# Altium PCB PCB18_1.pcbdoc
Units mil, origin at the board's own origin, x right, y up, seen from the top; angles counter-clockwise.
Board outline 2300 x 1655 mil, 2 copper layers (Top Layer, Bottom Layer); 38 components, 30 nets, 133 pads, 17 vias.
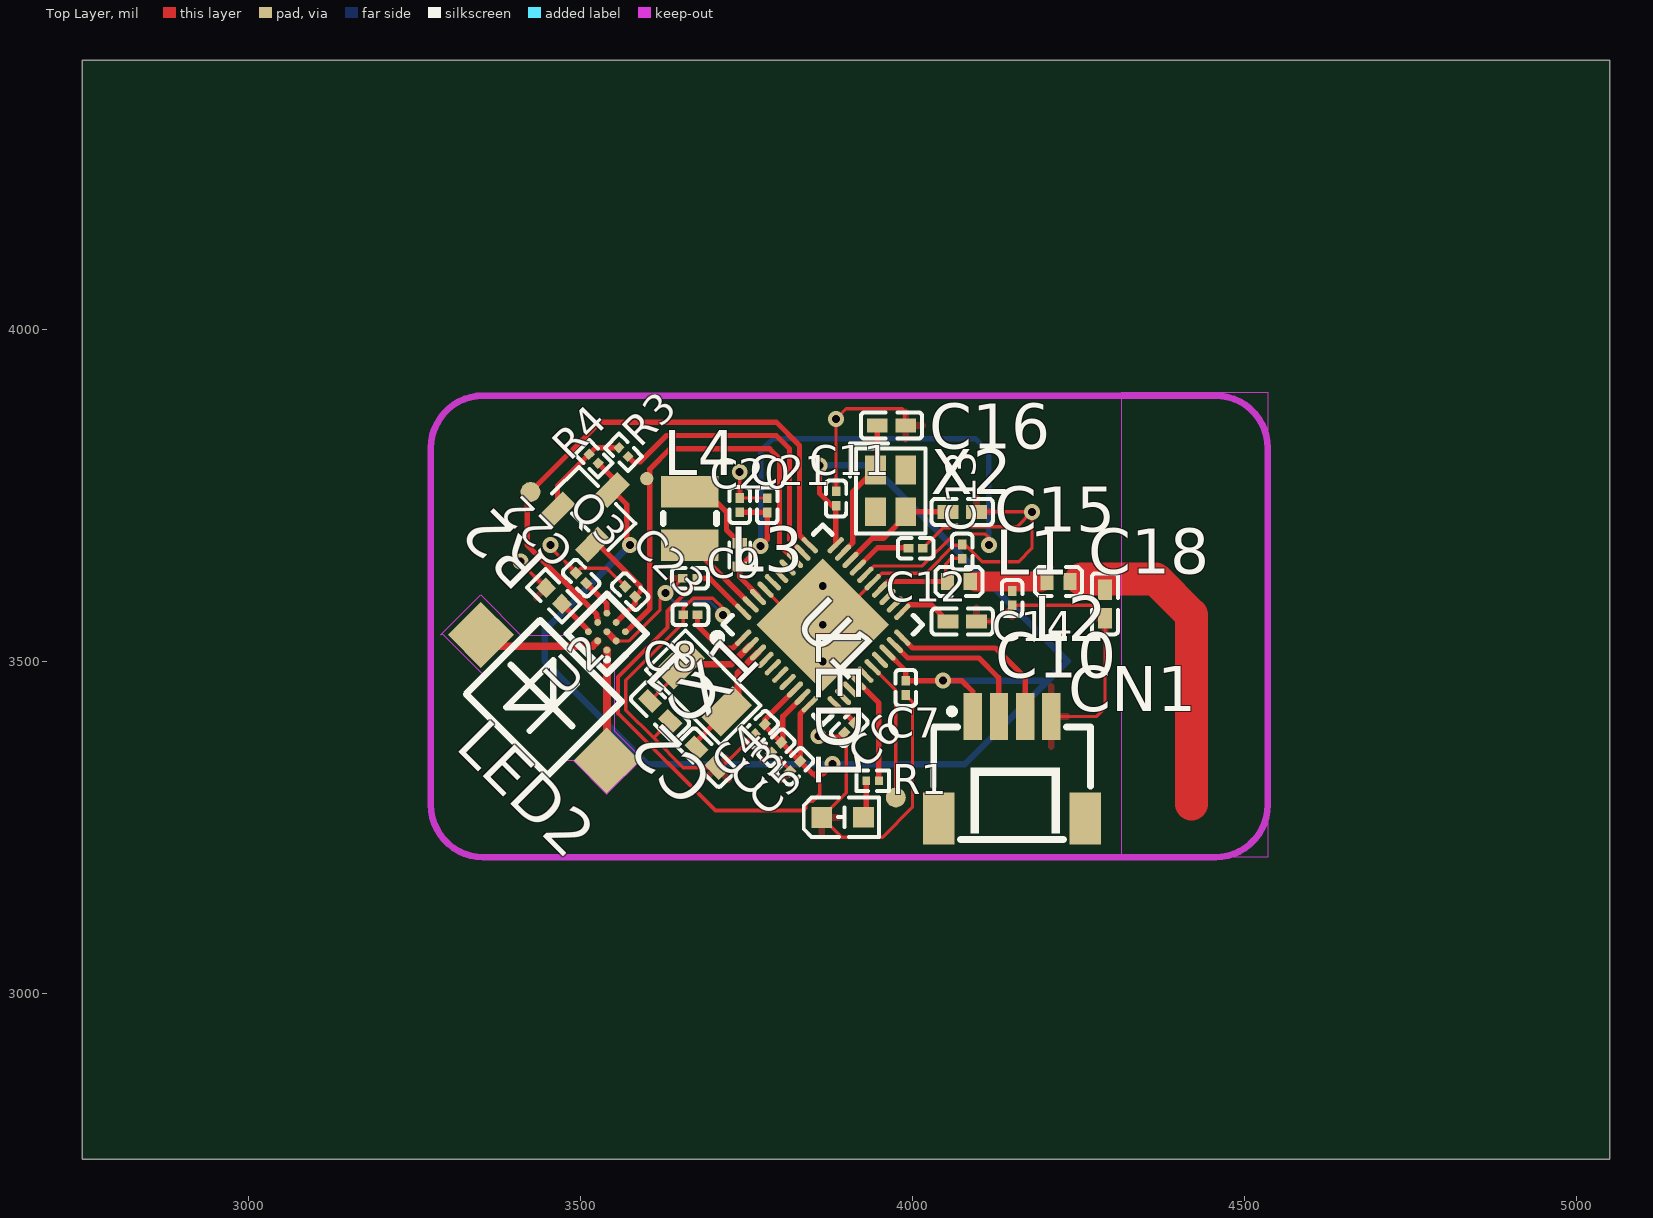
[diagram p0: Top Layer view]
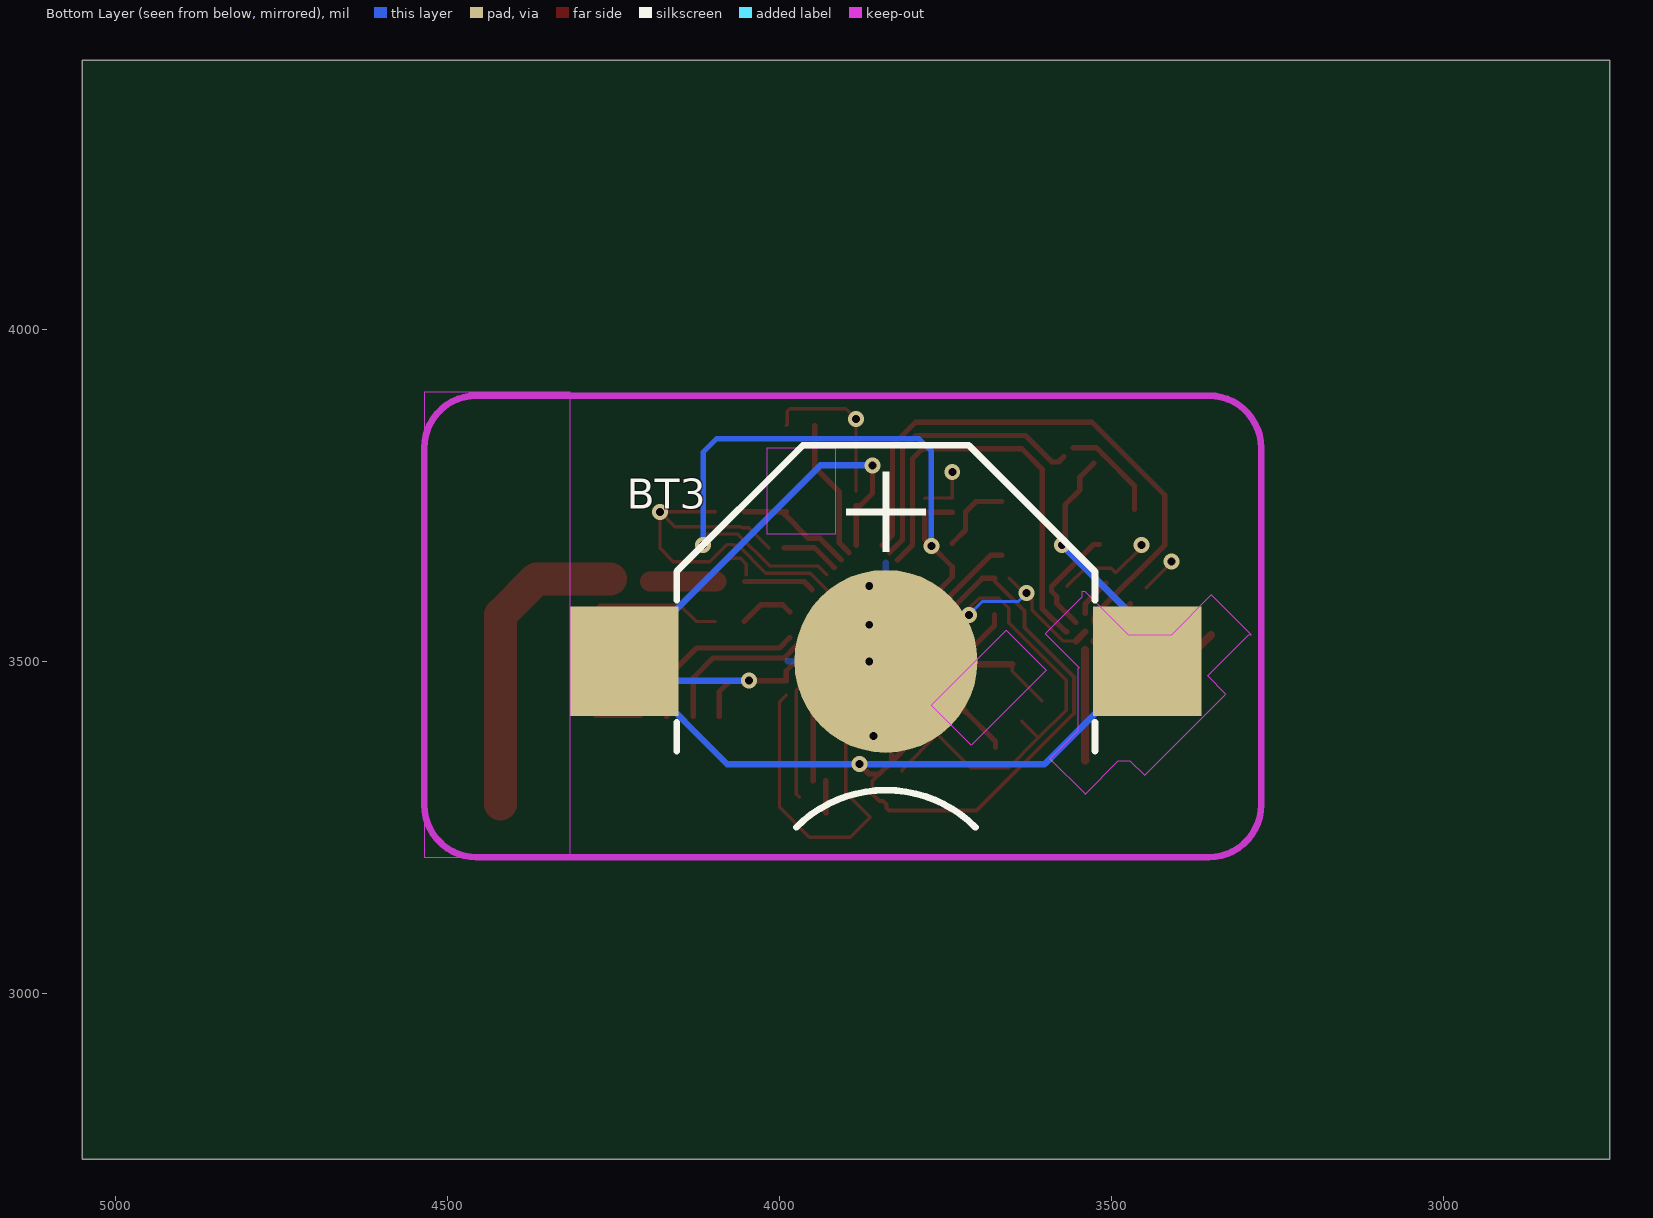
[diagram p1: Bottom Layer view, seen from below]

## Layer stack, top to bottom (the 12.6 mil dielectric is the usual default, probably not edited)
Top Layer: signal copper (thickness not stored)
Dielectric: dielectric 12.6, FR-4, Dk 4.8
Bottom Layer: signal copper (thickness not stored)

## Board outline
5050,2750 2750,2750 2750,4405 5050,4405

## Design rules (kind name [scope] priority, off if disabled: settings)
BoardOutlineClearance safeClearance [All] p0: genericclearance=10 ignorepadtopadclearanceinfootprint=FALSE except(0: Arc-SplitContinuation Track-SplitContinuation SMDPad-SplitContinuation THPad-SplitContinuation Via-SplitContinuation Fill-SplitContinuation Poly-SplitContinuation Region-SplitContinuation Text-SplitContinuation; 6: Track-CutoutEdge SMDPad-CutoutEdge THPad-CutoutEdge Via-CutoutEdge Fill-CutoutEdge Region-CutoutEdge; 11.8: Track-OutlineEdge SMDPad-OutlineEdge THPad-OutlineEdge Via-OutlineEdge Fill-OutlineEdge Region-OutlineEdge Poly-OutlineEdge Text-OutlineEdge)
Clearance safeClearance [(InNet('XL1') OR InNet('XL2') OR InNet('$1N2289') OR InNet('$1N2530') OR InNet('GND') OR InNet('$1N3495') OR InNet('SWDCLK') OR InNet('SWDIO') OR InNet('RESET') OR InNet('VDD_NRF') OR InNet('$1N2985') OR InNet('$1N3242') OR InNet('DEC4') OR InNet('XC1') OR InNet('XC2') OR InNet('DCC') OR InNet('$1N6091') OR InNet('E/CFGCLK') OR InNet('D/CFGDATA') OR InNet('$1N11204') OR InNet('$1N11226') OR InNet('$1N11357') OR InNet('$1N9430') OR InNet('$1N23087') OR InNet('$1N22902') OR InNet('LED') OR InNet('$1N29852') OR InNet('$1N28962') OR InNet('POWER_TS4231') OR InNet('$1N31595'))] p1: gap=7 ignorepadtopadclearanceinfootprint=FALSE except(6: Track-Track Track-SMDPad SMDPad-SMDPad Track-THPad SMDPad-THPad THPad-THPad Track-Via SMDPad-Via THPad-Via Via-Via Track-Fill SMDPad-Fill THPad-Fill Via-Fill Fill-Fill Track-Region SMDPad-Region THPad-Region Via-Region Fill-Region Region-Region Track-Poly SMDPad-Poly THPad-Poly Via-Poly Fill-Poly Region-Poly Poly-Poly Track-Text SMDPad-Text THPad-Text Via-Text Fill-Text Region-Text Poly-Text Text-Text Track-Hole SMDPad-Hole THPad-Hole Via-Hole Fill-Hole Region-Hole Poly-Hole Text-Hole; 11.8: Track-Sheet SMDPad-Sheet THPad-Sheet Via-Sheet Fill-Sheet Region-Sheet Poly-Sheet Text-Sheet Sheet-Hole)
DiffPairsRouting differentialPair [All] p1: maxuncoupledlength=10 minlimit=6 maxlimit=6 mostfreqgap=6 toplayer_minwidth=5 toplayer_prefwidth=10 toplayer_maxwidth=100 bottomlayer_minwidth=5 bottomlayer_prefwidth=10 bottomlayer_maxwidth=100
PasteMaskExpansion pasteMaskExpansion [All] p1: expansion=0
PlaneConnect innerPlane [All] p1: planeconnectstyle=Relief reliefexpansion=20 reliefentries=4 reliefconductorwidth=10 reliefairgap=10
PolygonConnect copperRegion [All] p1: connectstyle=Relief reliefentries=4 reliefconductorwidth=10 polygonreliefangle="90 Angle" airgapwidth=10
RoutingVias viaSize [All] p1: viastyle="Through Hole" holewidth=12 minholewidth=11.8 maxholewidth=236.2 width=24 minwidth=19.7 maxwidth=393.7
SolderMaskExpansion solderMaskExpansion [All] p1: useseparateexpansions=TRUE expansion=4 expansionbottom=4
Width trackWidth [All] p1: maxlimit=50 minlimit=5 preferedwidth=8

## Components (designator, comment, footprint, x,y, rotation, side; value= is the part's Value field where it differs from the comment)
BT3 "MY-1632-03" BAT-SMD_MY-1632-03 3840,3500 r180 bottom
C1 "GRM1555C1H120JA01D" C0402 3620,3425 r135 top
C2 "GRM1555C1H120JA01D" C0402 3690,3355 r135 top
C3 "GRM035R60J475ME15D" C0201 3795,3370 r225 top
C4 "GRM035R60J475ME15D" C0201 3770.13,3397.46 r225 top
C5 "GRM035R60J475ME15D" C0201 3823.28,3341.72 r225 top
C6 "GRM035R60J475ME15D" C0201 3905,3400 r225 top
C7 "GRM033R61E104KE14D" C0201 3990,3460 r90 top
C8 "GRM033R61E104KE14D" C0201 3665.6,3570 r180 top
C9 "GRM033R61A105ME44D" C0201 3665,3625 r180 top
C10 "CC0402KRX7R9BB821" C0402 4075,3560 r0 top
C11 "GRM033R61E104KE14D" C0201 3885,3745 r90 top
C12 "GRM033R61E104KE14D" C0201 4005,3670 r0 top
C13 "GRM0335C1H1R0BA01D" C0201 4075,3665 r90 top
C14 "GRM0335C1H1R2BA01D" C0201 4150,3595 r90 top
C15 "GRM1555C1H120JA01D" C0402 4075,3725 r0 top
C16 "GRM1555C1H120JA01D" C0402 3968.54,3855 r0 top
C18 "GRM1555C1H120JA01D" C0402 4290,3586.46 r90 top
C20 "CGA0201X5R473K160ET" C0201 3740,3735 r270 top
C21 "GRM033R61A105ME44D" C0201 3781.37,3734.88 r270 top
C22 "GRM033R61A105ME44D" C0201 3501.16,3625.33 r135 top
C23 "GRM033R61E104KE14D" C0201 3575,3605 r135 top
CN1 "1.0-4PWB" CONN-SMD_4P-P1.00_DEALON_1.0-4PWB 4150,3340 r0 top
L1 "LQW15AN4N7B00D" IND-SMD_L1.0-W0.6 4070,3620 r0 top
L2 "LQW15AN2N2B80D" IND-SMD_L1.0-W0.6 4220,3620 r0 top
L3 "LQW15AN15NG00D" IND-SMD_L1.0-W0.5-2 3740,3660 r270 top
L4 "FTC252012S100MBCA" IND-SMD_L2.5-W2.0 3665,3715 r90 top
LED1 "NCD0603G1" LED0603-RD_1 3895,3265 r0 top
LED2 "VBPW34S" SENSOR-SMD_L4.4-W3.9 3445,3445 r315 top
Q3 "HL3407A" SOT-23-3_L2.9-W1.3-P1.90-LS2.4-BL-1 3520,3730 r315 top
R1 "0201WMF1002TEE" R0201 3940,3320 r180 top
R2 "0402WGF1502TCE" R0402 3460.2,3598.51 r315 top
R3 "0201WMF1001TEE" R0201 3565,3815 r135 top
R4 "0201WMF1001TEE" R0201 3520,3805 r315 top
U1 "nRF52833-QDAA-R" QFN-40_L5.0-W5.0-P0.40-TL-EP3.6 3865,3555 r45 top
U2 "TS4231" TS4231 3540,3545 r135 top
X1 "X321532768KGD2SI" OSC-SMD_L3.2-W1.5 3685,3460.2 r135 top
X2 "X201632MOB4SI" CRYSTAL-SMD_4P-L2.0-W1.6-BL-2 3967.36,3756.49 r270 top

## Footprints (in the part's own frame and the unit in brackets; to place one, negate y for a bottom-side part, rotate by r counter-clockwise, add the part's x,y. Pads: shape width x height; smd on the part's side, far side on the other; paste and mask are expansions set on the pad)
BAT-SMD_MY-1632-03 [mm]
  rect 4.15x4.2 smd: 1(-10,0) 1(10,0)
  round 7 smd: 2(0,0)
  silkscreen extent -8,-6.35 8,8.25
C0201 [mil]
  rect 14.51x12.76 smd: 1(-10.8,0) 2(10.8,0)
  silkscreen extent -27,-15 27,15
C0402 [mm]
  rect 0.79x0.54 smd: 1(-0.545,0) 2(0.545,0)
  silkscreen extent -1.17,-0.5 1.17,0.5
CONN-SMD_4P-P1.00_DEALON_1.0-4PWB [mm]
  rect 0.7x1.8 smd: 1(-1.5,1.95) 2(-0.5,1.95) 3(0.5,1.95) 4(1.5,1.95)
  rect 1.2x2 smd: 5(2.8,-1.95) 6(-2.8,-1.95)
  silkscreen extent -3,-2.75 3,2.25
CRYSTAL-SMD_4P-L2.0-W1.6-BL-2 [mm]
  rect 1.1x0.8 smd: 1(-0.8,-0.575) 2(0.8,-0.575) 3(0.8,0.575) 4(-0.8,0.575)
  silkscreen extent -1.82,-1.56 1.64,1.33
IND-SMD_L1.0-W0.5-2 [mm]
  rect 0.4x0.55 smd: 1(-0.45,0) 2(0.45,0)
  silkscreen extent -0.5,-0.41 0.5,0.41
IND-SMD_L1.0-W0.6 [mm]
  rect 0.5x0.648 smd: 1(-0.434,0) 2(0.434,0)
  silkscreen extent -0.9,-0.55 0.9,0.55
IND-SMD_L2.5-W2.0 [mm]
  rect 1.2x2.2 smd: 1(1.028,0) 2(-1.028,0)
  silkscreen extent -0.2,-1.02 0.2,1.02
LED0603-RD_1 [mm]
  rect 0.8x0.8 smd: 1(-0.799,-0.004) 2(0.799,0.004)
  silkscreen extent -1.49,-0.75 1.39,0.76
OSC-SMD_L3.2-W1.5 [mm]
  rect 1.05x1.7 smd: 1(-1.275,0) 2(1.275,0)
  silkscreen extent -2.03,-1.08 2.03,1.08
QFN-40_L5.0-W5.0-P0.40-TL-EP3.6 [mm]
  oval 0.8x0.2 smd: 1(-2.499,1.8) 2(-2.499,1.4) 3(-2.499,1) 4(-2.499,0.6) 5(-2.499,0.2) 6(-2.499,-0.2) 7(-2.499,-0.6) 8(-2.499,-1) 9(-2.499,-1.4) 10(-2.499,-1.8) 21(2.499,-1.8) 22(2.499,-1.4) 23(2.499,-1) 24(2.499,-0.6) 25(2.499,-0.2) 26(2.499,0.2) 27(2.499,0.6) 28(2.499,1) 29(2.499,1.4) 30(2.499,1.8)
  oval 0.2x0.8 smd: 11(-1.8,-2.499) 12(-1.4,-2.499) 13(-1,-2.499) 14(-0.6,-2.499) 15(-0.2,-2.499) 16(0.2,-2.499) 17(0.6,-2.499) 18(1,-2.499) 19(1.4,-2.499) 20(1.8,-2.499) 31(1.8,2.499) 32(1.4,2.499) 33(1,2.499) 34(0.6,2.499) 35(0.2,2.499) 36(-0.2,2.499) 37(-0.6,2.499) 38(-1,2.499) 39(-1.4,2.499) 40(-1.8,2.499)
  rect 3.6x3.6 smd: 41(0,0)
  silkscreen extent -3.35,-2.7 2.7,2.7
R0201 [mil]
  rect 11.93x12.76 smd: 1(-9.51,0) 2(9.51,0)
  silkscreen extent -24,-15 24,15
R0402 [mm]
  rect 0.566x0.54 smd: 1(-0.433,0) 2(0.433,0)
  silkscreen extent -0.94,-0.5 0.94,0.5
SENSOR-SMD_L4.4-W3.9 [mm]
  rect 1.8x1.8 smd: 1(-3.4,0) 2(3.4,0)
  silkscreen extent -2.2,-2 2.2,2
SOT-23-3_L2.9-W1.3-P1.90-LS2.4-BL-1 [mm]
  rect 0.7x1.25 smd: 1(-0.95,-1) 2(0.95,-1) 3(0,1)
  silkscreen extent -1.53,-0.73 1.53,0.73
TS4231 [mil]
  round 10.31 smd: 1(-20,20) 2(-0.32,20) 3(19.37,20) 4(-20,0.32) 5(-0.32,0.32) 6(19.37,0.32) 7(-20,-19.37) 8(-0.32,-19.37) 9(19.37,-19.37)
  silkscreen extent -45,-40 40,45

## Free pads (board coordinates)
  round 30 smd: 1(3425,3755) 1(3975,3295)
  round 20 smd: 1(3600,3775)

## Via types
v1: diameter 24.02, hole 12.01, Top Layer to Bottom Layer, 17 vias

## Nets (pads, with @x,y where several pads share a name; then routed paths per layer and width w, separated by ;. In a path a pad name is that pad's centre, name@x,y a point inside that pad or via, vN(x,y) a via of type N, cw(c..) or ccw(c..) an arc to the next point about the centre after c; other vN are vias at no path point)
$1N2289: C10.1 U1.21 | length 83.6
  Top Layer w8: U1.21 3995.22,3585 4028.54,3585 C10.1
$1N2530: C13.1 L1.1 U1.24 | length 152
  Top Layer w5: L1.1@4050,3630 4050,3646.42 4058.58,3655 4074.2,3655 C13.1
  Top Layer w8: U1.24 3963.4,3620 L1.1
$1N2985: C14.2 L1.2 L2.1 | length 100
  Top Layer w30: L1.2@4095,3620 L2.1@4195,3620
$1N3242: C18.2 L2.2 | length 472.4
  Top Layer w50: 4255,3624.06 4365.94,3624.06 4420,3570 4420,3285
$1N3495: C12.1 U1.27 | length 87.6
  Top Layer w8: U1.27 3918.22,3641.63 ccw(c3909.3,3652.42) 3919.2,3642.52 3947.68,3671 C12.1@3993.2,3671
$1N6091: L3.1 L4.1 | length 117
  Top Layer w8: L4.1@3665,3740.48 3704.52,3740.48 3720,3725 3720,3697.72 L3.1
$1N9430: C22.1 U2.9 | length 58.2
  Top Layer w8: C22.1 3540,3586.49 U2.9
$1N11204: LED2.2 U2.1 | length 166.5
  Top Layer w12: LED2.2 3540,3350.69 U2.1
$1N11226: LED2.1 U2.2 | length 186.1
  Top Layer w12: LED2.1 3367.36,3522.64 3518.08,3522.64 U2.2
$1N11357: R2.2 U2.3 | length 58.4
  Top Layer w8: R2.2 3512.16,3546.55 U2.3
$1N22902: LED1.2 R1.2 | length 48.8
  Top Layer w8: LED1.2@3929.86,3271.47 3930.49,3272.1 R1.2
$1N23087: C8.1 U1.1 | length 105.7
  Top Layer w8: C8.1 3676.4,3553.6 3710,3520 3729.77,3520 U1.1
$1N28962: C23.1 Q3.2 U2.8 | length 167.5
  Top Layer w8: Q3.2 3527.45,3675.72 3590.64,3612.53 3590.64,3605.36 C23.1 3582.64,3587.19 U2.8
$1N29852: C6.1 U1.11 | length 39.6
  Top Layer w8: U1.11 3884.97,3435.31 C6.1
$1N31595: Q3.1 R3.2 R4.1 | length 152
  Top Layer w8: Q3.1 3465.72,3764.17 R4.1 3523.28,3821.72 R3.2
D/CFGDATA: pad.1@3425,3755 U1.31 U2.6 | length 862.4
  Top Layer w8: U2.6 3526.08,3564.88 3524.84,3566.11 3524.84,3570.16 3420,3675 3420,3750 3530,3860 3795,3860 3830,3825 3830,3690 3845.31,3674.69 U1.31
DCC: L4.2 U1.39 | length 122.1
  Top Layer w8: L4.2@3665,3659.52 3682.53,3659.52 U1.39
DEC4: C20.2 C21.2 L3.2 U1.26 U1.38 | length 1064.6
  Top Layer w5: U1.26 3942.37,3643.5 4014.95,3643.5 4063,3691.55 4110,3691.55 4115,3686.55 v1(4115,3675)
  Top Layer w8: C20.2 C21.2@3781.25,3724.2 ; U1.38 3767.58,3599.3 3740,3626.88 L3.2 v1(3771.47,3673.75) 3781.25,3683.53 C21.2@3781.25,3724.2 ; C21.2 C21.2@3781.25,3724.2
  Bottom Layer w8: v1(3771.47,3673.75) 3771.47,3816.47 3790,3835 4095,3835 4115,3815 v1(4115,3675)
E/CFGCLK: pad.1@3600,3775 U1.33 U2.7 | length 638.1
  Top Layer w8: U2.7 3569.55,3544.55 3604.64,3579.64 3604.64,3789.64 3635,3820 3785,3820 3800,3805 3800,3675 3822.58,3652.42 U1.33
GND: BT3.2 C1.1 C2.1 C3.2 C4.2 C5.2 C6.2 C7.1 C8.2 C9.2 C10.2 C11.2 C12.2 C13.2 C14.1 C15.2 C16.2 C18.1 C20.1 C21.1 C22.2 C23.2 CN1.4 LED1.1 R2.1 U1.25 U1.37 U1.41 U2.4 U2.5 | length 3205.5
  Top Layer w5: v1(3410,3650) 3410,3648.71 R2.1 ; v1(3455,3675) 3455,3671.49 C22.2 3500.63,3640.07 3539.93,3640.07 C23.2 ; U2.4 3573.31,3530.64 3620,3577.32 3620,3594.15 v1(3628.43,3602.58) 3631.78,3602.58 C9.2 ; C1.1 3610.24,3384.89 3610.24,3384.76 ; v1(3715,3570) 3715,3579.73 3699.73,3595 3670,3595 3654.8,3579.8 C8.2 3654.8,3557.88 3568.5,3471.58 3568.5,3426.5 3610.24,3384.76 ; v1(3740,3785) C20.1 3781.25,3745.8 C21.1 ; U1.37 3831.59,3555 v1(3865,3555) 3876.13,3555 U1.25 3953.63,3632.5 4020.53,3632.5 4062.52,3674.5 4068.7,3674.5 4070,3675.8 C13.2 4079.2,3675.8 4105,3650 4160,3650 4180,3670 v1(4180,3725) ; C5.2 3815.65,3336.67 C4.2 3712.5,3339.83 C2.1 3655.17,3339.83 3610.24,3384.76 ; v1(3858.39,3387.24) 3892.24,3387.24 C6.2 3900.51,3389.22 3900.51,3301.84 LED1.1 3893.38,3235 3955,3235 4000,3280 4000,3439.2 C7.1 ; C11.2 v1(3885,3865) 3900,3880 3985,3880 3988.54,3876.46 3988.54,3856.46 C16.2 ; C12.2 4046.62,3700.82 4056.72,3700.82 4058.45,3702.55 4157.55,3702.55 v1(4180,3725) ; C10.2 4125.8,3560 C14.1 4270.8,3584.2 C18.1 4290,3430 4276.77,3416.77 CN1.4 ; C15.2 v1(4180,3725)
  Top Layer w10: U2.5 U2.4
  Bottom Layer w5: v1(3628.43,3602.58) 3641.02,3590 3695,3590 v1(3715,3570)
  other v1: 3865,3500 3865,3613.08
LED: R1.1 U1.14 | length 161.8
  Top Layer w8: U1.14 3949.51,3437.08 R1.1
POWER_TS4231: R3.1 U1.32 | length 436
  Top Layer w8: R3.1 3580,3800 3590,3800 3630,3840 3795,3840 3815,3820 3815,3682.95 U1.32
RESET: pad.1@3975,3295 U1.16 | length 212.5
  Top Layer w5: U1.16 3975,3456.13 3975,3300 pad.1@3970,3295
SWDCLK: CN1.3 U1.20 | length 268.7
  Top Layer w8: U1.20 4000.22,3520 4125,3520 4170,3475 4170,3417.09 CN1.3
SWDIO: CN1.2 U1.19 | length 235.3
  Top Layer w8: U1.19 3992.95,3505 4100,3505 4130,3475 4130,3417.08 CN1.2
VDD_NRF: BT3.1 C3.1 C4.1 C5.1 C7.2 C9.1 C11.1 CN1.1 Q3.3 R4.2 U1.8 U1.9 U1.10 U1.18 U1.30 U1.40 | length 3416.4
  Top Layer w6: C9.1 3675.8,3620.24 3631.5,3575.94 3631.5,3550.84 3557,3476.34 3557,3421.74 3703.26,3275.48 3835.48,3275.48 3838.78,3278.78 3838.78,3284.33 3844.05,3289.61 3849.61,3289.61 3860.48,3300.48 3860.48,3319.79 3850,3330.27
  Top Layer w8: R4.2 3547.84,3777.16 Q3.3 3570,3735.68 3570,3680 v1(3575,3675) ; C9.1 3694.77,3625 U1.40 ; U1.8 3777.77,3412.1 C4.1 3777.77,3402.5 C3.1 ; U1.9 3805,3417.05 3805,3380 C3.1 ; U1.10 3830.92,3420.7 C5.1 ; v1(3860,3795) 3860,3753.03 3878.83,3734.2 C11.1 3884.46,3733.66 U1.30 ; v1(3880,3345) 3865.27,3330.27 3850,3330.27 C5.1 ; U1.18 3990,3485.68 C7.2 v1(4045.81,3470.8) 4074.2,3470.8 4090.94,3454.06 CN1.1 ; C3.1 C5.1
  Bottom Layer w10: v1(3575,3675) 3446.3,3546.3 3446.3,3500 3601.3,3345 v1(3880,3345) 4078.7,3345 BT3.1@4204.5,3470.8 ; v1(3860,3795) 3938.7,3795 4233.7,3500 BT3.1@4204.5,3470.8 ; v1(4045.81,3470.8) BT3.1@4204.5,3470.8
XC1: C15.1 U1.28 X2.3 | length 182.8
  Top Layer w8: U1.28 3939.32,3685 3956.27,3685 3992.76,3721.49 3992.76,3722.24 X2.3 C15.1
XC2: C16.1 U1.29 X2.1 | length 213.8
  Top Layer w8: U1.29 3910,3677.95 3910,3755 3942.99,3787.99 X2.1 3947.08,3790.35 C16.1
XL1: C1.2 U1.2 X1.2 | length 192.9
  Top Layer w5: C1.2 3649.5,3484.85 X1.2
  Top Layer w10: X1.2 3727.74,3495.7 U1.2
XL2: C2.2 U1.3 X1.1 | length 181.4
  Top Layer w8: C2.2 3674.83,3379.03 X1.1
  Top Layer w10: X1.1 3737.34,3441.54 3737.34,3482.66 U1.3@3767.76,3513.08
pads on no net: CN1.5 CN1.6 U1.4 U1.5 U1.6 U1.7 U1.12 U1.13 U1.15 U1.17 U1.22 U1.23 U1.34 U1.35 U1.36 X2.2 X2.4

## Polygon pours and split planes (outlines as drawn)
GND on Top Layer (solid, remove dead copper, pour order 0): 3120,4025 4645,4025 4645,3135 3120,3135
GND on Bottom Layer (solid, remove dead copper, pour order 2): 3000,4155 4800,4155 4800,3000 3000,3000

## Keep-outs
Board Outline Layer:
  region: 4315,3905 4535,3905 4535,3205 4315,3205
  region: 3915.06,3820.39 4019.66,3820.39 4019.66,3692.09 3915.06,3692.09
  region: 3658.55,3546.7 3598.5,3486.65 3711.45,3373.7 3771.5,3433.75 3660.25,3545 3660,3545 3658.55,3546.45
  region: 3600.1,3541.46 3549.02,3490.38 3550.74,3488.66 3550.74,3395.56 3592.87,3353.43 3540,3300.56 3540,3300 3490,3350 3472.49,3350 3450.56,3328.08 3328.08,3450.56 3355.57,3478.06 3293.63,3540 3290,3540 3350,3600 3410.54,3539.46 3474.46,3539.46 3540,3605 3545,3605 3545,3596.57
  lines w10: 3275,3283.74 ccw(c3353.74,3283.74) 3353.74,3205 4456.26,3205 ccw(c4456.26,3283.74) 4535,3283.74 4535,3821.26 ccw(c4456.26,3821.26) 4456.26,3900 3353.74,3900 ccw(c3353.74,3821.26) 3275,3821.26 3275,3283.74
